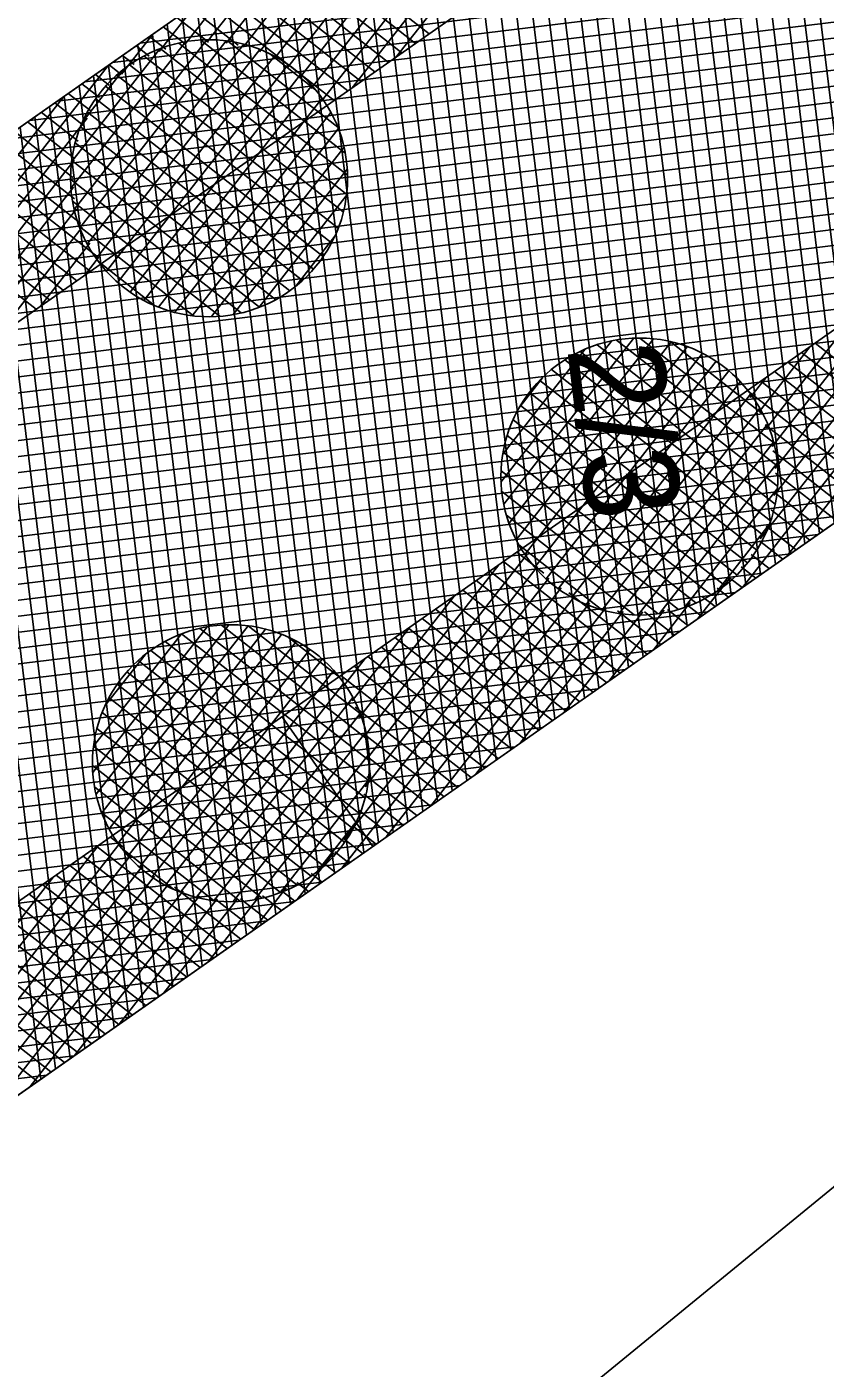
# Model space of a CAD drawing. Extents: x -566982 to -566809, y -1095912 to -1095685.
# Drawn here: x -566870.56 to -566860.47, y -1095812.81 to -1095795.86 of the extents above; entities that cross this region are included whole.
import ezdxf

# ---------------------------------------------------------------- set-up
doc = ezdxf.new("R2010")
doc.units = 0
for name, color, linetype in [('Vrstva 1', 7, 'Continuous'), ('Vrstva 40', 7, 'Continuous'), ('Vrstva 41', 7, 'Continuous'), ('Vrstva 42', 7, 'Continuous'), ('Vrstva 43', 7, 'Continuous'), ('Vrstva 44', 7, 'Continuous')]:
    doc.layers.add(name, color=color, linetype=linetype)

msp = doc.modelspace()

# ---------------------------------------------------------------- linework, layer by layer
at = {"layer": 'Vrstva 1'}
for p, q in [((-566887.09, -1095808.66), (-566860.75, -1095790.2)), ((-566853.9, -1095797.61), (-566880.71, -1095816.4)), ((-566865.42, -1095814.66), (-566845.99, -1095798.76))]:
    msp.add_line(p, q, dxfattribs=at)
at = {"layer": 'Vrstva 41'}
for p, q in [((-566863.902, -1095792.409), (-566867.103, -1095796.5)), ((-566864.464, -1095792.803), (-566867.258, -1095796.374)), ((-566865.026, -1095793.197), (-566867.429, -1095796.268)), ((-566865.589, -1095793.591), (-566867.615, -1095796.181)), ((-566864.495, -1095793.492), (-566866.961, -1095796.644)), ((-566864.581, -1095793.926), (-566866.835, -1095796.807)), ((-566866.151, -1095793.985), (-566867.818, -1095796.115)), ((-566864.573, -1095794.241), (-566866.447, -1095796.636)), ((-566866.713, -1095794.379), (-566868.038, -1095796.072)), ((-566864.521, -1095794.498), (-566865.885, -1095796.241)), ((-566867.276, -1095794.773), (-566868.28, -1095796.057)), ((-566867.292, -1095794.785), (-566865.645, -1095796.073)), ((-566867.121, -1095794.665), (-566865.474, -1095795.953)), ((-566867.463, -1095794.905), (-566865.816, -1095796.193)), ((-566867.805, -1095795.145), (-566866.159, -1095796.433)), ((-566867.634, -1095795.025), (-566865.987, -1095796.313)), ((-566867.838, -1095795.167), (-566868.557, -1095796.086)), ((-566867.977, -1095795.265), (-566866.33, -1095796.553)), ((-566868.148, -1095795.385), (-566866.501, -1095796.673)), ((-566868.4, -1095795.562), (-566868.883, -1095796.178)), ((-566868.49, -1095795.625), (-566867.885, -1095796.098)), ((-566868.319, -1095795.505), (-566866.672, -1095796.793)), ((-566868.661, -1095795.745), (-566868.261, -1095796.058)), ((-566868.963, -1095795.956), (-566869.359, -1095796.463)), ((-566869.004, -1095795.985), (-566868.798, -1095796.146)), ((-566868.833, -1095795.865), (-566868.551, -1095796.085)), ((-566869.175, -1095796.105), (-566869.01, -1095796.234)), ((-566869.346, -1095796.225), (-566869.197, -1095796.341)), ((-566869.525, -1095796.35), (-566871.764, -1095799.211)), ((-566869.689, -1095796.465), (-566869.509, -1095796.605)), ((-566869.517, -1095796.345), (-566869.363, -1095796.466)), ((-566869.86, -1095796.585), (-566869.637, -1095796.759)), ((-566870.087, -1095796.744), (-566871.958, -1095799.134)), ((-566870.202, -1095796.825), (-566869.838, -1095797.11)), ((-566870.031, -1095796.705), (-566869.747, -1095796.927)), ((-566869.794, -1095797.019), (-566871.584, -1095799.306)), ((-566870.374, -1095796.944), (-566869.907, -1095797.31)), ((-566870.716, -1095797.184), (-566869.972, -1095797.767)), ((-566870.545, -1095797.064), (-566869.953, -1095797.528)), ((-566870.887, -1095797.304), (-566869.952, -1095798.036)), ((-566871.058, -1095797.424), (-566869.874, -1095798.351)), ((-566869.956, -1095797.55), (-566871.42, -1095799.421)), ((-566871.401, -1095797.664), (-566869.754, -1095798.953)), ((-566871.23, -1095797.544), (-566869.647, -1095798.783)), ((-566871.572, -1095797.784), (-566869.925, -1095799.073)), ((-566871.914, -1095798.024), (-566870.268, -1095799.313)), ((-566871.743, -1095797.904), (-566870.096, -1095799.193)), ((-566869.967, -1095797.889), (-566871.27, -1095799.554)), ((-566872.086, -1095798.144), (-566870.439, -1095799.433)), ((-566869.929, -1095798.164), (-566871.134, -1095799.705)), ((-566869.856, -1095798.396), (-566870.946, -1095799.788)), ((-566869.761, -1095798.599), (-566870.383, -1095799.394)), ((-566869.649, -1095798.78), (-566869.821, -1095799)), ((-566859.717, -1095799.351), (-566861.139, -1095801.168)), ((-566860.095, -1095799.509), (-566861.21, -1095800.935)), ((-566859.591, -1095799.514), (-566861.101, -1095801.444)), ((-566859.449, -1095799.658), (-566861.116, -1095801.787)), ((-566859.123, -1095799.89), (-566861.515, -1095802.947)), ((-566859.294, -1095799.784), (-566861.289, -1095802.333)), ((-566860.597, -1095799.861), (-566858.951, -1095801.15)), ((-566860.657, -1095799.903), (-566861.304, -1095800.73)), ((-566858.936, -1095799.976), (-566860.953, -1095802.553)), ((-566860.768, -1095799.981), (-566859.122, -1095801.27)), ((-566861.111, -1095800.221), (-566859.464, -1095801.51)), ((-566860.94, -1095800.101), (-566859.293, -1095801.39)), ((-566861.219, -1095800.297), (-566861.417, -1095800.549)), ((-566861.282, -1095800.341), (-566859.635, -1095801.63)), ((-566861.453, -1095800.461), (-566859.807, -1095801.75)), ((-566861.228, -1095800.891), (-566859.978, -1095801.87)), ((-566861.129, -1095801.223), (-566860.149, -1095801.99)), ((-566861.097, -1095801.502), (-566860.32, -1095802.11)), ((-566861.11, -1095801.746), (-566860.491, -1095802.23)), ((-566861.151, -1095801.967), (-566860.663, -1095802.35)), ((-566861.216, -1095802.171), (-566860.834, -1095802.47)), ((-566861.301, -1095802.358), (-566861.005, -1095802.59)), ((-566864.23, -1095802.522), (-566866.254, -1095805.109)), ((-566864.364, -1095802.501), (-566864.025, -1095802.766)), ((-566861.406, -1095802.53), (-566861.176, -1095802.71)), ((-566864.594, -1095802.662), (-566866.288, -1095804.827)), ((-566864.103, -1095802.684), (-566866.279, -1095805.466)), ((-566864.706, -1095802.741), (-566863.059, -1095804.029)), ((-566864.535, -1095802.621), (-566862.888, -1095803.909)), ((-566861.53, -1095802.687), (-566861.347, -1095802.83)), ((-566863.961, -1095802.828), (-566866.552, -1095806.138)), ((-566864.877, -1095802.861), (-566863.231, -1095804.149)), ((-566861.684, -1095802.838), (-566862.078, -1095803.341)), ((-566861.673, -1095802.829), (-566861.519, -1095802.95)), ((-566863.805, -1095802.953), (-566866.576, -1095806.494)), ((-566865.156, -1095803.056), (-566866.354, -1095804.587)), ((-566863.634, -1095803.058), (-566866.014, -1095806.1)), ((-566865.22, -1095803.101), (-566863.573, -1095804.389)), ((-566865.048, -1095802.981), (-566863.402, -1095804.269)), ((-566863.707, -1095803.015), (-566862.717, -1095803.789)), ((-566862.018, -1095803.067), (-566861.861, -1095803.19)), ((-566861.835, -1095802.956), (-566861.69, -1095803.07)), ((-566863.447, -1095803.144), (-566865.452, -1095805.706)), ((-566865.391, -1095803.221), (-566863.744, -1095804.509)), ((-566863.244, -1095803.209), (-566864.889, -1095805.312)), ((-566863.023, -1095803.251), (-566864.327, -1095804.918)), ((-566862.773, -1095803.256), (-566863.765, -1095804.524)), ((-566862.502, -1095803.235), (-566863.202, -1095804.13)), ((-566863.093, -1095803.241), (-566862.546, -1095803.669)), ((-566862.75, -1095803.255), (-566862.375, -1095803.55)), ((-566862.173, -1095803.139), (-566862.64, -1095803.735)), ((-566862.462, -1095803.227), (-566862.203, -1095803.43)), ((-566862.224, -1095803.16), (-566862.032, -1095803.31)), ((-566865.718, -1095803.451), (-566866.446, -1095804.38)), ((-566865.562, -1095803.341), (-566863.915, -1095804.629)), ((-566865.904, -1095803.581), (-566864.258, -1095804.869)), ((-566865.733, -1095803.461), (-566864.087, -1095804.749)), ((-566866.076, -1095803.701), (-566864.429, -1095804.989)), ((-566866.281, -1095803.845), (-566866.555, -1095804.195)), ((-566866.418, -1095803.941), (-566864.771, -1095805.229)), ((-566866.247, -1095803.821), (-566864.6, -1095805.109)), ((-566866.589, -1095804.061), (-566864.943, -1095805.349)), ((-566866.406, -1095804.458), (-566865.114, -1095805.469)), ((-566866.293, -1095804.801), (-566865.285, -1095805.589)), ((-566866.256, -1095805.083), (-566865.456, -1095805.709)), ((-566866.261, -1095805.334), (-566865.627, -1095805.829)), ((-566866.299, -1095805.558), (-566865.799, -1095805.949)), ((-566866.361, -1095805.763), (-566865.97, -1095806.069)), ((-566866.443, -1095805.953), (-566866.141, -1095806.189)), ((-566869.5, -1095806.101), (-566869.33, -1095806.233)), ((-566866.545, -1095806.127), (-566866.312, -1095806.309)), ((-566869.655, -1095806.21), (-566871.072, -1095808.02)), ((-566869.245, -1095806.335), (-566871.048, -1095808.64)), ((-566869.374, -1095806.175), (-566871.035, -1095808.298)), ((-566869.842, -1095806.341), (-566868.195, -1095807.629)), ((-566869.671, -1095806.221), (-566868.024, -1095807.509)), ((-566866.688, -1095806.313), (-566867.139, -1095806.888)), ((-566866.666, -1095806.287), (-566866.483, -1095806.429)), ((-566869.1, -1095806.474), (-566871.222, -1095809.186)), ((-566870.013, -1095806.461), (-566868.367, -1095807.749)), ((-566866.804, -1095806.432), (-566866.655, -1095806.549)), ((-566868.941, -1095806.595), (-566871.638, -1095810.041)), ((-566870.217, -1095806.604), (-566871.144, -1095807.788)), ((-566870.184, -1095806.581), (-566868.538, -1095807.869)), ((-566867.143, -1095806.675), (-566866.997, -1095806.789)), ((-566866.963, -1095806.562), (-566866.826, -1095806.669)), ((-566868.767, -1095806.697), (-566871.075, -1095809.647)), ((-566870.527, -1095806.821), (-566868.88, -1095808.109)), ((-566868.578, -1095806.781), (-566870.513, -1095809.253)), ((-566870.356, -1095806.701), (-566868.709, -1095807.989)), ((-566868.373, -1095806.843), (-566869.951, -1095808.859)), ((-566868.688, -1095806.736), (-566867.853, -1095807.389)), ((-566867.279, -1095806.743), (-566867.701, -1095807.283)), ((-566867.576, -1095806.844), (-566867.339, -1095807.029)), ((-566867.346, -1095806.77), (-566867.168, -1095806.909)), ((-566870.698, -1095806.941), (-566869.051, -1095808.229)), ((-566868.149, -1095806.882), (-566869.388, -1095808.465)), ((-566867.895, -1095806.881), (-566868.826, -1095808.071)), ((-566867.619, -1095806.853), (-566868.263, -1095807.677)), ((-566868.183, -1095806.877), (-566867.682, -1095807.269)), ((-566867.854, -1095806.88), (-566867.511, -1095807.149)), ((-566871.04, -1095807.181), (-566869.394, -1095808.469)), ((-566870.869, -1095807.061), (-566869.223, -1095808.349)), ((-566871.212, -1095807.301), (-566869.565, -1095808.589)), ((-566871.287, -1095807.495), (-566869.736, -1095808.709)), ((-566871.109, -1095807.889), (-566869.908, -1095808.829)), ((-566871.042, -1095808.195), (-566870.079, -1095808.949)), ((-566871.033, -1095808.456), (-566870.25, -1095809.069)), ((-566871.056, -1095808.692), (-566870.421, -1095809.189))]:
    msp.add_line(p, q, dxfattribs=at)
at = {"layer": 'Vrstva 42'}
msp.add_line((-566866.184, -1095806.219), (-566867.331, -1095804.581), dxfattribs=at)
for points in [[(-566834.15, -1095760.69), (-566836.072, -1095760.136), (-566841.286, -1095779.189), (-566855.268, -1095796.126), (-566881.984, -1095814.851), (-566891.818, -1095824.318), (-566954.342, -1095716.292), (-566956.66, -1095716.28), (-566892.27, -1095827.53), (-566880.71, -1095816.4), (-566853.9, -1095797.61), (-566839.47, -1095780.13)], [(-566945.07, -1095716.34), (-566947.388, -1095716.328), (-566890.462, -1095814.681), (-566885.816, -1095810.21), (-566859.382, -1095791.684), (-566846.734, -1095776.361), (-566841.831, -1095758.448), (-566843.76, -1095757.92), (-566848.55, -1095775.42), (-566860.75, -1095790.2), (-566887.09, -1095808.66), (-566890.01, -1095811.47)]]:
    msp.add_lwpolyline(points, close=True, dxfattribs=at)
at = {"layer": 'Vrstva 43'}
for p, q in [((-566861.173, -1095790.496), (-566859.8, -1095801.745)), ((-566861.358, -1095790.626), (-566859.986, -1095801.875)), ((-566861.73, -1095790.887), (-566860.357, -1095802.135)), ((-566861.544, -1095790.756), (-566860.171, -1095802.005)), ((-566861.915, -1095791.017), (-566860.543, -1095802.265)), ((-566862.101, -1095791.147), (-566860.728, -1095802.396)), ((-566862.472, -1095791.407), (-566861.099, -1095802.656)), ((-566862.286, -1095791.277), (-566860.914, -1095802.526)), ((-566862.658, -1095791.537), (-566861.285, -1095802.786)), ((-566862.843, -1095791.667), (-566861.471, -1095802.916)), ((-566863.215, -1095791.927), (-566861.842, -1095803.176)), ((-566863.029, -1095791.797), (-566861.656, -1095803.046)), ((-566863.4, -1095792.057), (-566862.027, -1095803.306)), ((-566863.586, -1095792.187), (-566862.213, -1095803.436)), ((-566863.771, -1095792.317), (-566862.399, -1095803.566)), ((-566864.143, -1095792.578), (-566862.77, -1095803.827)), ((-566863.957, -1095792.448), (-566862.584, -1095803.696)), ((-566864.328, -1095792.708), (-566862.955, -1095803.957)), ((-566864.514, -1095792.838), (-566863.141, -1095804.087)), ((-566864.885, -1095793.098), (-566863.512, -1095804.347)), ((-566864.699, -1095792.968), (-566863.327, -1095804.217)), ((-566865.071, -1095793.228), (-566863.698, -1095804.477)), ((-566865.256, -1095793.358), (-566863.884, -1095804.607)), ((-566865.627, -1095793.618), (-566864.255, -1095804.867)), ((-566865.442, -1095793.488), (-566864.069, -1095804.737)), ((-566865.813, -1095793.748), (-566864.44, -1095804.997)), ((-566869.126, -1095796.07), (-566850.781, -1095793.832)), ((-566865.999, -1095793.878), (-566864.626, -1095805.127)), ((-566869.474, -1095796.314), (-566850.966, -1095794.056)), ((-566866.37, -1095794.139), (-566864.997, -1095805.388)), ((-566866.184, -1095794.009), (-566864.812, -1095805.257)), ((-566869.822, -1095796.558), (-566851.151, -1095794.28)), ((-566866.555, -1095794.269), (-566865.183, -1095805.518)), ((-566866.741, -1095794.399), (-566865.368, -1095805.648)), ((-566870.17, -1095796.802), (-566851.336, -1095794.504)), ((-566866.927, -1095794.529), (-566865.554, -1095805.778)), ((-566870.519, -1095797.046), (-566851.521, -1095794.728)), ((-566867.298, -1095794.789), (-566865.925, -1095806.038)), ((-566867.112, -1095794.659), (-566865.74, -1095805.908)), ((-566870.867, -1095797.29), (-566851.706, -1095794.952)), ((-566867.484, -1095794.919), (-566866.111, -1095806.168)), ((-566867.669, -1095795.049), (-566866.296, -1095806.298)), ((-566871.215, -1095797.534), (-566851.891, -1095795.176)), ((-566868.04, -1095795.309), (-566866.668, -1095806.558)), ((-566867.855, -1095795.179), (-566866.482, -1095806.428)), ((-566871.563, -1095797.778), (-566852.076, -1095795.4)), ((-566868.226, -1095795.439), (-566866.853, -1095806.688)), ((-566871.911, -1095798.022), (-566852.261, -1095795.624)), ((-566868.412, -1095795.57), (-566867.039, -1095806.818)), ((-566868.783, -1095795.83), (-566867.41, -1095807.079)), ((-566868.597, -1095795.7), (-566867.224, -1095806.949)), ((-566872.259, -1095798.266), (-566852.446, -1095795.848)), ((-566868.968, -1095795.96), (-566867.596, -1095807.209)), ((-566872.607, -1095798.51), (-566852.631, -1095796.072)), ((-566869.154, -1095796.09), (-566867.781, -1095807.339)), ((-566872.955, -1095798.754), (-566852.815, -1095796.296)), ((-566869.34, -1095796.22), (-566867.967, -1095807.469)), ((-566869.711, -1095796.48), (-566868.338, -1095807.729)), ((-566869.525, -1095796.35), (-566868.153, -1095807.599)), ((-566873.303, -1095798.998), (-566853, -1095796.52)), ((-566869.896, -1095796.61), (-566868.524, -1095807.859)), ((-566873.652, -1095799.242), (-566853.185, -1095796.744)), ((-566870.082, -1095796.74), (-566868.709, -1095807.989)), ((-566874, -1095799.486), (-566853.37, -1095796.968)), ((-566870.453, -1095797), (-566869.081, -1095808.249)), ((-566870.268, -1095796.87), (-566868.895, -1095808.119)), ((-566870.639, -1095797.13), (-566869.266, -1095808.38)), ((-566874.348, -1095799.73), (-566853.555, -1095797.192)), ((-566870.825, -1095797.261), (-566869.452, -1095808.51)), ((-566874.696, -1095799.974), (-566853.74, -1095797.417)), ((-566871.196, -1095797.521), (-566869.823, -1095808.77)), ((-566871.01, -1095797.391), (-566869.637, -1095808.64)), ((-566875.044, -1095800.218), (-566853.947, -1095797.643)), ((-566871.381, -1095797.651), (-566870.009, -1095808.9)), ((-566871.567, -1095797.781), (-566870.194, -1095809.03)), ((-566875.392, -1095800.462), (-566854.296, -1095797.887)), ((-566871.753, -1095797.911), (-566870.38, -1095809.16)), ((-566875.74, -1095800.706), (-566854.644, -1095798.131)), ((-566876.088, -1095800.95), (-566854.992, -1095798.375)), ((-566876.436, -1095801.194), (-566855.34, -1095798.619)), ((-566876.784, -1095801.438), (-566855.688, -1095798.863)), ((-566877.133, -1095801.681), (-566856.036, -1095799.107)), ((-566877.481, -1095801.925), (-566856.384, -1095799.351)), ((-566877.829, -1095802.169), (-566856.732, -1095799.595)), ((-566878.177, -1095802.413), (-566857.08, -1095799.839)), ((-566878.525, -1095802.657), (-566857.428, -1095800.083)), ((-566878.873, -1095802.901), (-566857.776, -1095800.327)), ((-566879.221, -1095803.145), (-566858.125, -1095800.571)), ((-566879.569, -1095803.389), (-566858.473, -1095800.815)), ((-566879.917, -1095803.633), (-566858.821, -1095801.059)), ((-566880.265, -1095803.877), (-566859.169, -1095801.303)), ((-566880.614, -1095804.121), (-566859.517, -1095801.547)), ((-566880.962, -1095804.365), (-566859.865, -1095801.791)), ((-566881.31, -1095804.609), (-566860.213, -1095802.035)), ((-566881.658, -1095804.853), (-566860.561, -1095802.279)), ((-566882.006, -1095805.097), (-566860.909, -1095802.523)), ((-566882.354, -1095805.341), (-566861.257, -1095802.766)), ((-566882.702, -1095805.585), (-566861.605, -1095803.01)), ((-566883.05, -1095805.829), (-566861.954, -1095803.254)), ((-566883.398, -1095806.073), (-566862.302, -1095803.498)), ((-566883.747, -1095806.317), (-566862.65, -1095803.742)), ((-566884.095, -1095806.561), (-566862.998, -1095803.986)), ((-566884.443, -1095806.805), (-566863.346, -1095804.23)), ((-566884.791, -1095807.049), (-566863.694, -1095804.474)), ((-566885.139, -1095807.293), (-566864.042, -1095804.718)), ((-566885.487, -1095807.537), (-566864.39, -1095804.962)), ((-566885.835, -1095807.781), (-566864.738, -1095805.206)), ((-566886.183, -1095808.025), (-566865.086, -1095805.45)), ((-566886.531, -1095808.268), (-566865.434, -1095805.694)), ((-566886.879, -1095808.512), (-566865.783, -1095805.938)), ((-566887.185, -1095808.751), (-566866.131, -1095806.182)), ((-566887.425, -1095808.982), (-566866.479, -1095806.426)), ((-566887.664, -1095809.213), (-566866.827, -1095806.67)), ((-566887.904, -1095809.443), (-566867.175, -1095806.914)), ((-566888.144, -1095809.674), (-566867.523, -1095807.158)), ((-566888.384, -1095809.905), (-566867.871, -1095807.402)), ((-566888.623, -1095810.136), (-566868.219, -1095807.646)), ((-566888.863, -1095810.366), (-566868.567, -1095807.89)), ((-566889.103, -1095810.597), (-566868.915, -1095808.134)), ((-566889.343, -1095810.828), (-566869.263, -1095808.378)), ((-566889.583, -1095811.059), (-566869.612, -1095808.622)), ((-566889.822, -1095811.289), (-566869.96, -1095808.866)), ((-566900.779, -1095812.828), (-566870.308, -1095809.109))]:
    msp.add_line(p, q, dxfattribs=at)
msp.add_lwpolyline([(-566834.15, -1095760.69), (-566843.76, -1095757.92), (-566848.55, -1095775.42), (-566860.75, -1095790.2), (-566887.09, -1095808.66), (-566890.01, -1095811.47), (-566945.07, -1095716.34), (-566956.66, -1095716.28), (-566892.27, -1095827.53), (-566880.71, -1095816.4), (-566853.9, -1095797.61), (-566839.47, -1095780.13)], close=True, dxfattribs=at)
at = {"layer": 'Vrstva 44'}
for p, q in [((-566868.552, -1095796.053), (-566869.997, -1095797.9)), ((-566868.875, -1095796.142), (-566869.988, -1095797.564)), ((-566868.279, -1095796.029), (-566869.957, -1095798.174)), ((-566868.035, -1095796.042), (-566869.884, -1095798.405)), ((-566867.815, -1095796.085), (-566869.791, -1095798.61)), ((-566867.612, -1095796.15), (-566869.679, -1095798.791)), ((-566868.869, -1095796.14), (-566866.517, -1095797.98)), ((-566868.633, -1095796.071), (-566866.504, -1095797.737)), ((-566868.358, -1095796.032), (-566866.534, -1095797.459)), ((-566868.017, -1095796.045), (-566866.628, -1095797.131)), ((-566867.425, -1095796.236), (-566869.549, -1095798.95)), ((-566867.254, -1095796.342), (-566869.406, -1095799.091)), ((-566869.074, -1095796.233), (-566866.557, -1095798.203)), ((-566867.486, -1095796.206), (-566866.907, -1095796.659)), ((-566869.33, -1095796.399), (-566869.849, -1095797.061)), ((-566869.417, -1095796.473), (-566866.707, -1095798.593)), ((-566869.256, -1095796.345), (-566866.621, -1095798.407)), ((-566867.097, -1095796.466), (-566869.248, -1095799.215)), ((-566869.561, -1095796.614), (-566866.811, -1095798.766)), ((-566866.954, -1095796.607), (-566869.077, -1095799.32)), ((-566869.684, -1095796.772), (-566866.933, -1095798.924)), ((-566866.825, -1095796.767), (-566868.89, -1095799.406)), ((-566869.789, -1095796.943), (-566867.073, -1095799.069)), ((-566866.713, -1095796.948), (-566868.687, -1095799.471)), ((-566869.877, -1095797.129), (-566867.233, -1095799.198)), ((-566866.62, -1095797.154), (-566868.466, -1095799.514)), ((-566869.944, -1095797.33), (-566867.413, -1095799.31)), ((-566866.548, -1095797.386), (-566868.221, -1095799.525)), ((-566869.987, -1095797.551), (-566867.616, -1095799.406)), ((-566866.509, -1095797.661), (-566867.947, -1095799.499)), ((-566870.001, -1095797.793), (-566867.848, -1095799.478)), ((-566866.519, -1095797.999), (-566867.622, -1095799.408)), ((-566869.977, -1095798.066), (-566868.118, -1095799.521)), ((-566869.891, -1095798.387), (-566868.45, -1095799.515)), ((-566866.665, -1095798.51), (-566867.158, -1095799.14)), ((-566869.646, -1095798.833), (-566868.941, -1095799.384)), ((-566863.17, -1095799.834), (-566864.565, -1095801.617)), ((-566862.889, -1095799.8), (-566864.529, -1095801.896)), ((-566862.64, -1095799.806), (-566864.463, -1095802.136)), ((-566862.416, -1095799.844), (-566864.372, -1095802.344)), ((-566863.35, -1095799.882), (-566861.071, -1095801.666)), ((-566863.104, -1095799.821), (-566861.074, -1095801.409)), ((-566862.81, -1095799.797), (-566861.121, -1095801.118)), ((-566862.429, -1095799.841), (-566861.256, -1095800.759)), ((-566863.507, -1095799.941), (-566864.543, -1095801.264)), ((-566862.211, -1095799.907), (-566864.263, -1095802.529)), ((-566862.021, -1095799.989), (-566864.138, -1095802.693)), ((-566863.566, -1095799.967), (-566861.103, -1095801.894)), ((-566861.846, -1095800.09), (-566863.996, -1095802.837)), ((-566863.925, -1095800.194), (-566861.237, -1095802.298)), ((-566861.687, -1095800.211), (-566863.841, -1095802.963)), ((-566863.757, -1095800.071), (-566861.159, -1095802.104)), ((-566864.042, -1095800.299), (-566864.327, -1095800.664)), ((-566864.074, -1095800.332), (-566861.334, -1095802.475)), ((-566861.542, -1095800.35), (-566863.671, -1095803.071)), ((-566864.205, -1095800.483), (-566861.451, -1095802.638)), ((-566861.411, -1095800.507), (-566863.488, -1095803.161)), ((-566864.318, -1095800.648), (-566861.585, -1095802.787)), ((-566861.295, -1095800.683), (-566863.288, -1095803.231)), ((-566864.412, -1095800.829), (-566861.737, -1095802.922)), ((-566861.198, -1095800.884), (-566863.07, -1095803.276)), ((-566864.485, -1095801.026), (-566861.908, -1095803.042)), ((-566864.537, -1095801.238), (-566862.104, -1095803.143)), ((-566861.123, -1095801.113), (-566862.831, -1095803.295)), ((-566861.076, -1095801.377), (-566862.562, -1095803.277)), ((-566864.564, -1095801.472), (-566862.324, -1095803.224)), ((-566864.555, -1095801.733), (-566862.579, -1095803.279)), ((-566861.074, -1095801.7), (-566862.248, -1095803.2)), ((-566864.495, -1095802.033), (-566862.884, -1095803.294)), ((-566861.175, -1095802.153), (-566861.829, -1095802.989)), ((-566864.338, -1095802.41), (-566863.29, -1095803.23)), ((-566868.278, -1095803.445), (-566869.72, -1095805.287)), ((-566868.005, -1095803.42), (-566869.68, -1095805.561)), ((-566867.761, -1095803.432), (-566869.608, -1095805.793)), ((-566868.096, -1095803.423), (-566866.254, -1095804.864)), ((-566867.76, -1095803.432), (-566866.344, -1095804.54)), ((-566868.602, -1095803.534), (-566869.711, -1095804.951)), ((-566867.54, -1095803.475), (-566869.514, -1095805.998)), ((-566867.337, -1095803.54), (-566869.403, -1095806.18)), ((-566867.15, -1095803.625), (-566869.274, -1095806.34)), ((-566868.806, -1095803.629), (-566866.282, -1095805.605)), ((-566868.603, -1095803.534), (-566866.241, -1095805.383)), ((-566868.368, -1095803.464), (-566866.227, -1095805.14)), ((-566867.249, -1095803.578), (-566866.606, -1095804.081)), ((-566869.062, -1095803.797), (-566869.568, -1095804.444)), ((-566866.979, -1095803.731), (-566869.13, -1095806.481)), ((-566868.987, -1095803.742), (-566866.348, -1095805.807)), ((-566869.148, -1095803.87), (-566866.435, -1095805.993)), ((-566866.822, -1095803.855), (-566868.973, -1095806.604)), ((-566869.29, -1095804.013), (-566866.54, -1095806.165)), ((-566866.678, -1095803.996), (-566868.802, -1095806.71)), ((-566869.412, -1095804.171), (-566866.662, -1095806.323)), ((-566866.549, -1095804.156), (-566868.615, -1095806.796)), ((-566869.517, -1095804.343), (-566866.803, -1095806.467)), ((-566866.437, -1095804.337), (-566868.412, -1095806.862)), ((-566869.603, -1095804.529), (-566866.964, -1095806.594)), ((-566866.344, -1095804.542), (-566868.192, -1095806.905)), ((-566869.67, -1095804.731), (-566867.146, -1095806.706)), ((-566866.271, -1095804.774), (-566867.947, -1095806.916)), ((-566869.711, -1095804.953), (-566867.349, -1095806.801)), ((-566866.232, -1095805.048), (-566867.673, -1095806.891)), ((-566869.724, -1095805.197), (-566867.583, -1095806.872)), ((-566869.697, -1095805.472), (-566867.854, -1095806.914)), ((-566866.241, -1095805.385), (-566867.349, -1095806.801)), ((-566869.607, -1095805.796), (-566868.19, -1095806.905)), ((-566866.384, -1095805.893), (-566866.889, -1095806.538)), ((-566869.344, -1095806.256), (-566868.703, -1095806.758))]:
    msp.add_line(p, q, dxfattribs=at)
for centre in [(-566868.253, -1095797.777), (-566862.816, -1095801.546), (-566867.976, -1095805.168)]:
    msp.add_circle(centre, 1.75, dxfattribs=at)

# ---------------------------------------------------------------- texts
at = {"layer": 'Vrstva 40'}
msp.add_text('2/3', height=1.2, rotation=276.9575, dxfattribs=at).set_placement((-566863.73, -1095799.925))

doc.saveas('drawing.dxf')
